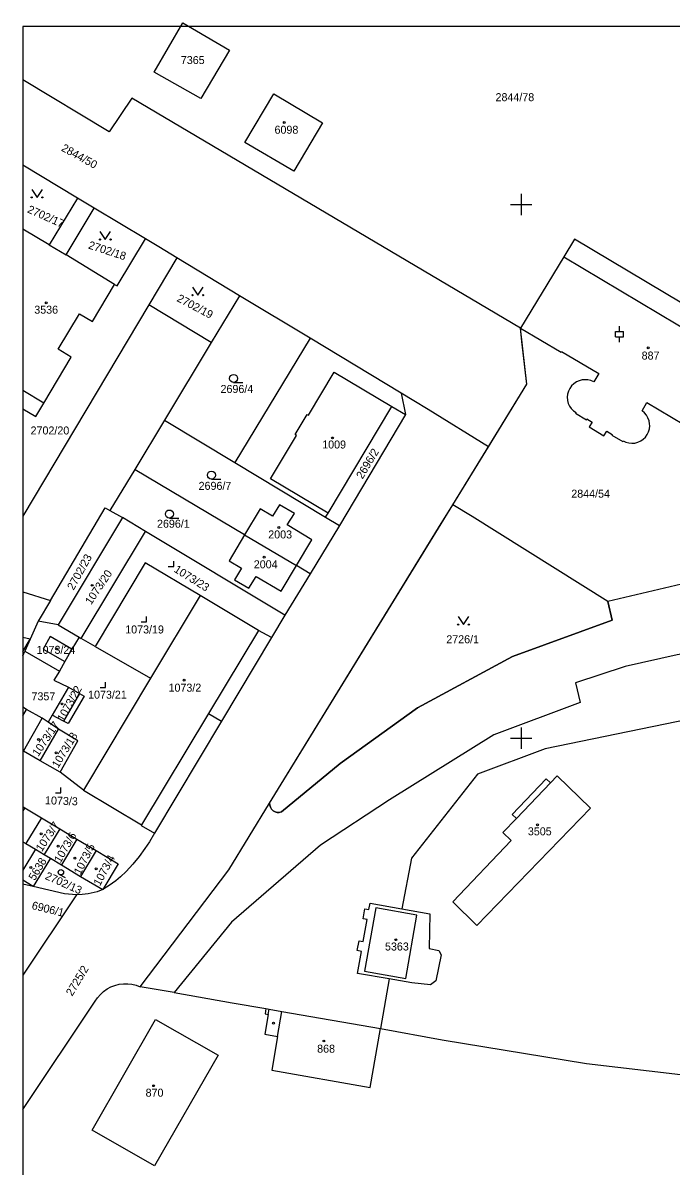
# Model space of a CAD drawing. Extents: x -800194 to -799078, y -1007177 to -1006597.
# Drawn here: x -800193.4 to -800071.9, y -1006980.2 to -1006766 of the extents above; entities that cross this region are included whole.
import ezdxf

# ---------------------------------------------------------------- set-up
doc = ezdxf.new("R2010")
doc.units = 0
for name, color, linetype in [('Legenda 1', 7, 'Continuous'), ('Ramove udaje', 7, 'Continuous'), ('Vrstva 53', 7, 'Continuous'), ('Vrstva 55', 7, 'Continuous'), ('Vrstva 56', 7, 'Continuous'), ('Vrstva 57', 7, 'Continuous'), ('Vrstva 58', 7, 'Continuous'), ('Vrstva 59', 7, 'Continuous')]:
    doc.layers.add(name, color=color, linetype=linetype)

msp = doc.modelspace()

# ---------------------------------------------------------------- linework, layer by layer
at = {"layer": 'Legenda 1'}
msp.add_lwpolyline([(-800193.4, -1007176.65), (-799312.4, -1007176.65), (-799312.4, -1006766.65), (-800193.4, -1006766.65)], close=True, dxfattribs=at)
at = {"layer": 'Ramove udaje'}
for p, q in [((-800100, -1006798), (-800100, -1006802)), ((-800102, -1006800), (-800100, -1006800)), ((-800100, -1006800), (-800098, -1006800)), ((-800100, -1006898), (-800100, -1006902)), ((-800102, -1006900), (-800100, -1006900)), ((-800100, -1006900), (-800098, -1006900))]:
    msp.add_line(p, q, dxfattribs=at)
at = {"layer": 'Vrstva 53'}
msp.add_lwpolyline([(-800067.83, -1006870.66), (-800083.75, -1006874.38), (-800082.93, -1006877.89), (-800101.58, -1006884.73), (-800119.41, -1006894.35), (-800133.89, -1006904.78), (-800144.92, -1006913.85), (-800145.32, -1006913.94), (-800145.72, -1006913.94), (-800146.12, -1006913.83), (-800146.47, -1006913.63), (-800146.77, -1006913.35), (-800147, -1006912.99), (-800147.12, -1006912.61), (-800147.15, -1006912.2), (-800112.81, -1006856.29), (-800098.93, -1006833.67), (-800100.11, -1006823.15), (-800172.96, -1006780.08), (-800177.22, -1006786.39), (-800193.4, -1006776.62)], dxfattribs=at)
at = {"layer": 'Vrstva 55'}
for p, q in [((-800183.18, -1006798.79), (-800193.4, -1006792.65)), ((-800180.01, -1006800.69), (-800183.18, -1006798.79)), ((-800170.41, -1006806.46), (-800180.01, -1006800.69)), ((-800164.51, -1006810.02), (-800169.77, -1006818.83)), ((-800152.8, -1006817.1), (-800164.51, -1006810.02)), ((-800152.8, -1006817.1), (-800158.09, -1006825.87)), ((-800139.57, -1006825.06), (-800152.8, -1006817.1)), ((-800158.09, -1006825.87), (-800169.77, -1006818.83)), ((-800158.09, -1006825.87), (-800166.86, -1006840.41)), ((-800139.57, -1006825.06), (-800153.65, -1006848.37)), ((-800122.47, -1006835.35), (-800139.57, -1006825.06)), ((-800122.47, -1006835.35), (-800121.67, -1006839.36)), ((-800166.86, -1006840.41), (-800172.41, -1006849.68)), ((-800166.86, -1006840.41), (-800153.65, -1006848.37)), ((-800121.67, -1006839.36), (-800134.05, -1006860.17)), ((-800112.81, -1006856.29), (-800106.13, -1006845.4)), ((-800172.41, -1006849.68), (-800177.12, -1006857.35)), ((-800153.65, -1006848.37), (-800136.64, -1006858.61)), ((-800177.12, -1006857.35), (-800174.74, -1006858.64)), ((-800136.64, -1006858.61), (-800134.05, -1006860.17)), ((-800174.74, -1006858.64), (-800186.75, -1006878.76)), ((-800170.43, -1006861.26), (-800174.74, -1006858.64)), ((-800134.05, -1006860.17), (-800139.55, -1006869.21)), ((-800182.47, -1006881.33), (-800170.43, -1006861.26)), ((-800144.27, -1006876.97), (-800170.43, -1006861.26)), ((-800151.83, -1006861.89), (-800142.1, -1006867.68)), ((-800139.55, -1006869.21), (-800144.27, -1006876.97)), ((-800139.55, -1006869.21), (-800142.1, -1006867.68)), ((-800067.83, -1006870.66), (-800083.75, -1006874.38)), ((-800193.4, -1006872.57), (-800188.22, -1006874.2)), ((-800160.18, -1006873.27), (-800169.49, -1006888.81)), ((-800188.22, -1006874.2), (-800190.53, -1006878.1)), ((-800144.27, -1006876.97), (-800146.81, -1006881.14)), ((-800190.53, -1006878.1), (-800192.02, -1006881.48)), ((-800186.75, -1006878.76), (-800190.53, -1006878.1)), ((-800186.75, -1006878.76), (-800182.83, -1006881.12)), ((-800192.02, -1006881.48), (-800193.4, -1006881.15)), ((-800192.02, -1006881.48), (-800193.01, -1006883.73)), ((-800182.83, -1006881.12), (-800182.47, -1006881.33)), ((-800179.85, -1006882.84), (-800182.47, -1006881.33)), ((-800193.4, -1006884.61), (-800193.01, -1006883.73)), ((-800193.01, -1006883.73), (-800186.55, -1006887.44)), ((-800179.85, -1006882.84), (-800169.49, -1006888.81)), ((-800186.55, -1006887.44), (-800187.59, -1006889.15)), ((-800184.82, -1006890.46), (-800187.9, -1006895.7)), ((-800187.59, -1006889.15), (-800184.82, -1006890.46)), ((-800169.49, -1006888.81), (-800182.05, -1006909.75)), ((-800192.7, -1006894.63), (-800193.4, -1006894.24)), ((-800193.4, -1006895.86), (-800192.7, -1006894.63)), ((-800189.78, -1006896.28), (-800192.7, -1006894.63)), ((-800193.28, -1006902.47), (-800189.78, -1006896.28)), ((-800188.68, -1006897.03), (-800189.78, -1006896.28)), ((-800187.9, -1006895.7), (-800188.68, -1006897.03)), ((-800186.7, -1006898.36), (-800188.68, -1006897.03)), ((-800190.15, -1006904.25), (-800186.7, -1006898.36)), ((-800183.1, -1006900.51), (-800186.7, -1006898.36)), ((-800186.38, -1006906.38), (-800183.1, -1006900.51)), ((-800193.28, -1006902.47), (-800193.4, -1006902.4)), ((-800190.15, -1006904.25), (-800193.28, -1006902.47)), ((-800186.38, -1006906.38), (-800190.15, -1006904.25)), ((-800182.05, -1006909.75), (-800186.38, -1006906.38)), ((-800193.05, -1006913.06), (-800193.4, -1006913.64)), ((-800193.05, -1006913.06), (-800189.92, -1006914.94)), ((-800189.92, -1006914.94), (-800192.83, -1006919.78)), ((-800189.92, -1006914.94), (-800186.48, -1006917.01)), ((-800186.48, -1006917.01), (-800189.39, -1006921.85)), ((-800186.48, -1006917.01), (-800183.26, -1006918.94)), ((-800193.4, -1006919.44), (-800192.83, -1006919.78)), ((-800192.83, -1006919.78), (-800191.06, -1006920.85)), ((-800183.26, -1006918.94), (-800186.17, -1006923.78)), ((-800183.26, -1006918.94), (-800179.67, -1006921.09)), ((-800191.06, -1006920.85), (-800193.4, -1006924.74)), ((-800188.23, -1006922.55), (-800191.44, -1006927.83)), ((-800191.06, -1006920.85), (-800189.39, -1006921.85)), ((-800189.39, -1006921.85), (-800188.23, -1006922.55)), ((-800188.23, -1006922.55), (-800186.17, -1006923.78)), ((-800179.67, -1006921.09), (-800182.6, -1006925.93)), ((-800120.56, -1006922.5), (-800122.37, -1006932)), ((-800186.17, -1006923.78), (-800182.6, -1006925.93)), ((-800191.44, -1006927.83), (-800193.4, -1006926.67)), ((-800182.6, -1006925.93), (-800178.43, -1006928.42)), ((-800191.44, -1006927.83), (-800193.4, -1006927.37)), ((-800183.37, -1006929.41), (-800193.4, -1006944.43)), ((-800124.76, -1006945.16), (-800126.38, -1006954.46)), ((-800165.04, -1006947.7), (-800171.39, -1006946.62))]:
    msp.add_line(p, q, dxfattribs=at)
for points in [[(-800163.38, -1006765.95), (-800154.63, -1006771.06), (-800160.01, -1006780.11), (-800168.77, -1006775.17), (-800163.38, -1006765.95)], [(-800100.11, -1006823.15), (-800172.96, -1006780.08), (-800177.22, -1006786.39), (-800193.4, -1006776.62)], [(-800146.37, -1006779.25), (-800137.24, -1006784.69), (-800142.62, -1006793.72), (-800151.76, -1006788.38), (-800146.37, -1006779.25)], [(-800183.18, -1006798.79), (-800188.44, -1006807.58), (-800193.4, -1006804.6)], [(-800176.19, -1006814.96), (-800185.31, -1006809.46), (-800180.01, -1006800.69)], [(-800176.19, -1006814.96), (-800175.72, -1006815.24), (-800170.41, -1006806.46)], [(-800164.51, -1006810.02), (-800167.92, -1006807.96), (-800170.41, -1006806.46)], [(-800020.66, -1006847.86), (-800026.06, -1006844.58), (-800089.97, -1006806.47), (-800092.01, -1006809.83), (-800100.11, -1006823.15)], [(-800193.4, -1006838.29), (-800190.96, -1006839.75), (-800189.46, -1006837.23), (-800184.32, -1006828.6), (-800186.75, -1006827.14), (-800182.78, -1006820.48), (-800180.34, -1006821.93), (-800176.19, -1006814.96)], [(-800169.77, -1006818.83), (-800193.4, -1006858.41)], [(-800106.13, -1006845.4), (-800098.93, -1006833.67), (-800099.83, -1006825.69), (-800100.11, -1006823.15)], [(-800100.11, -1006823.15), (-800092.48, -1006827.68), (-800092.4, -1006827.53), (-800085.43, -1006831.67), (-800086.36, -1006833.24)], [(-800086.36, -1006833.24), (-800086.9, -1006833.01), (-800087.46, -1006832.87), (-800088.05, -1006832.83), (-800088.53, -1006832.88), (-800089.09, -1006833.02), (-800089.63, -1006833.26), (-800090.11, -1006833.59), (-800090.53, -1006833.99), (-800090.88, -1006834.46), (-800091.13, -1006834.97), (-800091.29, -1006835.52), (-800091.35, -1006836.09), (-800091.31, -1006836.66), (-800091.3, -1006836.72), (-800091.15, -1006837.27), (-800090.91, -1006837.79), (-800090.58, -1006838.25), (-800090.17, -1006838.66), (-800089.7, -1006838.98)], [(-800106.13, -1006845.4), (-800117.43, -1006838.45), (-800120.08, -1006836.82), (-800122.47, -1006835.35)], [(-800077.33, -1006838.69), (-800076.4, -1006837.12), (-800069.48, -1006841.22), (-800069.56, -1006841.35), (-800061.89, -1006845.9), (-800061.61, -1006845.43), (-800053.39, -1006850.31), (-800053.68, -1006850.78), (-800042.78, -1006857.25)], [(-800136.64, -1006858.61), (-800136.18, -1006857.85), (-800124.24, -1006837.87), (-800121.67, -1006839.36)], [(-800089.7, -1006838.98), (-800089.78, -1006839.11), (-800087.76, -1006840.33), (-800087.69, -1006840.2), (-800086.68, -1006840.8), (-800087.24, -1006841.68), (-800084.46, -1006843.37), (-800083.93, -1006842.46), (-800082.91, -1006843.08), (-800082.98, -1006843.21), (-800080.94, -1006844.44), (-800080.86, -1006844.31)], [(-800080.86, -1006844.31), (-800080.34, -1006844.55), (-800079.78, -1006844.7), (-800079.21, -1006844.75), (-800078.65, -1006844.71), (-800078.09, -1006844.56), (-800077.57, -1006844.32), (-800077.09, -1006843.99), (-800076.68, -1006843.59), (-800076.35, -1006843.12), (-800076.1, -1006842.6), (-800075.95, -1006842.04), (-800075.89, -1006841.47), (-800075.91, -1006841.1), (-800076.01, -1006840.53), (-800076.22, -1006839.99), (-800076.51, -1006839.49), (-800076.89, -1006839.06), (-800077.33, -1006838.69)], [(-800151.83, -1006861.89), (-800172.32, -1006849.75), (-800172.41, -1006849.68)], [(-800142.1, -1006867.68), (-800139.22, -1006862.87), (-800143.86, -1006860.02), (-800142.5, -1006857.92), (-800145.28, -1006856.27), (-800146.57, -1006858.42), (-800148.9, -1006857.02), (-800151.83, -1006861.89)], [(-800147.15, -1006912.2), (-800114.97, -1006859.8), (-800112.81, -1006856.29)], [(-800083.75, -1006874.38), (-800109.15, -1006858.49), (-800112.81, -1006856.29)], [(-800188.22, -1006874.2), (-800177.98, -1006856.88), (-800177.12, -1006857.35)], [(-800151.83, -1006861.89), (-800154.75, -1006866.76), (-800152.43, -1006868.16), (-800153.72, -1006870.34), (-800151.03, -1006871.91), (-800149.68, -1006869.74), (-800144.98, -1006872.49), (-800142.1, -1006867.68)], [(-800160.18, -1006873.27), (-800170.48, -1006867.17), (-800179.85, -1006882.84)], [(-800146.81, -1006881.14), (-800149.24, -1006879.83), (-800160.18, -1006873.27)], [(-800144.92, -1006913.85), (-800133.89, -1006904.78), (-800119.41, -1006894.35), (-800101.58, -1006884.73), (-800082.93, -1006877.89), (-800083.75, -1006874.38)], [(-799964.79, -1006890.84), (-799979.01, -1006885.96), (-799998.45, -1006881.67), (-800018.08, -1006879.48), (-800038.51, -1006879.76), (-800056.43, -1006881.95), (-800070.76, -1006884.38), (-800080.47, -1006886.59), (-800089.79, -1006889.63), (-800088.91, -1006893.34), (-800105.12, -1006899.41), (-800124.67, -1006911.59), (-800137.62, -1006920.11), (-800154.3, -1006934.53), (-800165.04, -1006947.7)], [(-800193.4, -1006883.76), (-800192.02, -1006881.48)], [(-800182.83, -1006881.12), (-800184.21, -1006883.32), (-800185.51, -1006885.63), (-800186.55, -1006887.44)], [(-800146.81, -1006881.14), (-800156.19, -1006896.85), (-800168.72, -1006917.84)], [(-800184.82, -1006890.46), (-800182.76, -1006891.66), (-800181.9, -1006892.16), (-800184.93, -1006897.3), (-800185.8, -1006896.83), (-800187.9, -1006895.7)], [(-800048.34, -1006892.35), (-800095.49, -1006902.03), (-800108.2, -1006906.76), (-800120.56, -1006922.5)], [(-800094.49, -1006908.41), (-800093.24, -1006907.11), (-800087, -1006913.15), (-800108.28, -1006935.11), (-800112.78, -1006930.68), (-800101.83, -1006919.22), (-800103.39, -1006917.73), (-800100.86, -1006915.08), (-800101.66, -1006914.32), (-800095.28, -1006907.65), (-800094.49, -1006908.41)], [(-800182.05, -1006909.75), (-800171.15, -1006916.28), (-800171.22, -1006916.39), (-800168.72, -1006917.84)], [(-800171.39, -1006946.62), (-800154.78, -1006924.73), (-800147.15, -1006912.2)], [(-800147.15, -1006912.2), (-800147.12, -1006912.61), (-800147, -1006912.99), (-800146.78, -1006913.34), (-800146.77, -1006913.35), (-800146.47, -1006913.63), (-800146.12, -1006913.83), (-800145.72, -1006913.94), (-800145.32, -1006913.94), (-800144.92, -1006913.85)], [(-800193.4, -1006912.85), (-800193.05, -1006913.06)], [(-800168.72, -1006917.84), (-800169.66, -1006919.43), (-800170.52, -1006920.73), (-800171.62, -1006922.22), (-800172.79, -1006923.65), (-800174.04, -1006925.01), (-800175.11, -1006926.02), (-800176, -1006926.76), (-800177.19, -1006927.63), (-800178.43, -1006928.42)], [(-800179.67, -1006921.09), (-800175.54, -1006923.58), (-800178.43, -1006928.42)], [(-800183.37, -1006929.41), (-800185.59, -1006929.21), (-800191.44, -1006927.83)], [(-800178.43, -1006928.42), (-800179.48, -1006928.81), (-800180.04, -1006928.97), (-800181.14, -1006929.22), (-800182.25, -1006929.36), (-800183.37, -1006929.41)], [(-800124.76, -1006945.16), (-800130.67, -1006944.14), (-800129.93, -1006939.99), (-800130.7, -1006939.85), (-800130.36, -1006937.99), (-800129.59, -1006938.12), (-800128.86, -1006934.02), (-800129.62, -1006933.9), (-800129.29, -1006932.03), (-800128.52, -1006932.16), (-800128.31, -1006930.95), (-800122.37, -1006932)], [(-800122.37, -1006932), (-800117.1, -1006932.94), (-800117.23, -1006939.43), (-800115.39, -1006939.82), (-800114.95, -1006940.64), (-800115.98, -1006945.49), (-800117, -1006946.26), (-800120.48, -1006945.9), (-800124.76, -1006945.16)], [(-800179.84, -1006949.35), (-800179.39, -1006948.67), (-800178.86, -1006948.05), (-800178.26, -1006947.5), (-800177.6, -1006947.03), (-800176.89, -1006946.65), (-800176.16, -1006946.36), (-800175.37, -1006946.16), (-800174.56, -1006946.05), (-800173.75, -1006946.05), (-800172.94, -1006946.14), (-800172.15, -1006946.33), (-800171.39, -1006946.62)], [(-800165.04, -1006947.7), (-800154.15, -1006949.62), (-800147.83, -1006950.72)], [(-800193.4, -1006969.65), (-800179.84, -1006949.35)], [(-800147.83, -1006950.72), (-800148, -1006951.71), (-800147.41, -1006951.81), (-800148.05, -1006955.52), (-800145.68, -1006955.92), (-800146.75, -1006962.28), (-800128.29, -1006965.5), (-800126.38, -1006954.46)], [(-800147.83, -1006950.72), (-800147.24, -1006950.83), (-800144.85, -1006951.24), (-800126.38, -1006954.46)], [(-800156.78, -1006959.44), (-800168.69, -1006980.17), (-800180.42, -1006973.53), (-800168.51, -1006952.75), (-800156.78, -1006959.44)], [(-800126.38, -1006954.46), (-800114.82, -1006956.57), (-800087.75, -1006960.99), (-799990.59, -1006972.38), (-799910.85, -1006981.15)]]:
    msp.add_lwpolyline(points, dxfattribs=at)
at = {"layer": 'Vrstva 56'}
for p, q in [((-800188.44, -1006807.58), (-800185.31, -1006809.46)), ((-800092.01, -1006809.83), (-800054.01, -1006832.46)), ((-800139.86, -1006839.49), (-800135.03, -1006831.4)), ((-800135.03, -1006831.4), (-800124.24, -1006837.87)), ((-800189.46, -1006837.23), (-800193.4, -1006834.87)), ((-800142.38, -1006843.12), (-800140.12, -1006839.33)), ((-800140.12, -1006839.33), (-800139.86, -1006839.49)), ((-800146.98, -1006851.4), (-800142.12, -1006843.27)), ((-800142.12, -1006843.27), (-800142.38, -1006843.12)), ((-800136.18, -1006857.85), (-800146.98, -1006851.4)), ((-800149.24, -1006879.83), (-800158.6, -1006895.39)), ((-800188.29, -1006880.97), (-800189.61, -1006883.33)), ((-800184.21, -1006883.32), (-800188.29, -1006880.97)), ((-800189.61, -1006883.33), (-800185.51, -1006885.63)), ((-800182.76, -1006891.66), (-800185.8, -1006896.83)), ((-800158.6, -1006895.39), (-800171.15, -1006916.28)), ((-800158.6, -1006895.39), (-800156.19, -1006896.85)), ((-800100.86, -1006915.08), (-800094.49, -1006908.41)), ((-800127.23, -1006931.83), (-800129.33, -1006943.68)), ((-800119.52, -1006933.21), (-800127.23, -1006931.83)), ((-800121.59, -1006945.08), (-800119.52, -1006933.21)), ((-800129.33, -1006943.68), (-800121.59, -1006945.08)), ((-800147.41, -1006951.81), (-800147.24, -1006950.83)), ((-800145.68, -1006955.92), (-800144.85, -1006951.24))]:
    msp.add_line(p, q, dxfattribs=at)
at = {"layer": 'Vrstva 58'}
for p, q in [((-800082.29, -1006823.83), (-800080.79, -1006823.83)), ((-800082.29, -1006824.83), (-800082.29, -1006823.83)), ((-800081.54, -1006823.83), (-800081.54, -1006822.83)), ((-800080.79, -1006824.83), (-800080.79, -1006823.83)), ((-800082.29, -1006824.83), (-800080.79, -1006824.83)), ((-800081.54, -1006825.83), (-800081.54, -1006824.83)), ((-800153.9, -1006833.35), (-800152.15, -1006833.35)), ((-800158.04, -1006851.47), (-800156.29, -1006851.47)), ((-800165.92, -1006858.76), (-800164.17, -1006858.76)), ((-800165.12, -1006867.84), (-800165.12, -1006866.84)), ((-800166.13, -1006867.84), (-800165.12, -1006867.84)), ((-800170.24, -1006878.2), (-800170.24, -1006877.2)), ((-800171.24, -1006878.2), (-800170.24, -1006878.2)), ((-800178.93, -1006890.56), (-800177.92, -1006890.56)), ((-800177.92, -1006890.56), (-800177.92, -1006889.56)), ((-800186.28, -1006910.27), (-800186.28, -1006909.27)), ((-800187.28, -1006910.27), (-800186.28, -1006910.27)), ((-800186.51, -1006925.6), (-800185.47, -1006926.15))]:
    msp.add_line(p, q, dxfattribs=at)
for points in [[(-800191.74, -1006797.17), (-800190.74, -1006798.67), (-800189.74, -1006797.17)], [(-800178.94, -1006805.05), (-800177.94, -1006806.55), (-800176.94, -1006805.05)], [(-800161.61, -1006815.49), (-800160.61, -1006816.99), (-800159.61, -1006815.49)], [(-800111.8, -1006877.25), (-800110.8, -1006878.75), (-800109.8, -1006877.25)]]:
    msp.add_lwpolyline(points, dxfattribs=at)
for centre, radius in [((-800191.74, -1006798.67), 0.1), ((-800189.74, -1006798.67), 0.1), ((-800178.94, -1006806.55), 0.1), ((-800176.94, -1006806.55), 0.1), ((-800161.61, -1006816.99), 0.1), ((-800159.61, -1006816.99), 0.1), ((-800153.9, -1006832.6), 0.75), ((-800158.04, -1006850.72), 0.75), ((-800165.92, -1006858.01), 0.75), ((-800111.8, -1006878.75), 0.1), ((-800109.8, -1006878.75), 0.1), ((-800186.27, -1006925.16), 0.502)]:
    msp.add_circle(centre, radius, dxfattribs=at)
at = {"layer": 'Vrstva 59'}
for centre in [(-800144.39, -1006784.64), (-800189.01, -1006818.41), (-800076.15, -1006826.87), (-800135.34, -1006843.76), (-800145.42, -1006860.54), (-800148.15, -1006866.1), (-800180.42, -1006871.38), (-800187.09, -1006883.31), (-800163.18, -1006889.16), (-800186.06, -1006893.62), (-800190.48, -1006900.28), (-800187.14, -1006902.79), (-800096.93, -1006916.27), (-800189.96, -1006917.94), (-800186.79, -1006920.28), (-800183.63, -1006922.51), (-800191.89, -1006924.28), (-800179.65, -1006924.5), (-800123.47, -1006937.8), (-800146.41, -1006953.43), (-800136.95, -1006956.79), (-800168.88, -1006965.17)]:
    msp.add_circle(centre, 0.175, dxfattribs=at)

# ---------------------------------------------------------------- texts
at = {"layer": 'Vrstva 57'}
for s, p in [('7365', (-800163.78, -1006773.67)), ('2844/78', (-800104.79, -1006780.63)), ('6098', (-800146.22, -1006786.73)), ('3536', (-800191.26, -1006820.46)), ('887', (-800077.4, -1006829.06)), ('2696/4', (-800156.34, -1006835.32)), ('2702/20', (-800191.95, -1006843.1)), ('1009', (-800137.28, -1006845.73)), ('2696/7', (-800160.45, -1006853.48)), ('2844/54', (-800090.59, -1006854.95)), ('2696/1', (-800168.25, -1006860.58)), ('2003', (-800147.4, -1006862.59)), ('2004', (-800150.11, -1006868.19)), ('1073/19', (-800174.21, -1006880.4)), ('2726/1', (-800114.02, -1006882.24)), ('1073/24', (-800190.82, -1006884.22)), ('1073/2', (-800166.09, -1006891.31)), ('7357', (-800191.78, -1006892.93)), ('1073/21', (-800181.17, -1006892.62)), ('3505', (-800098.73, -1006918.24)), ('5363', (-800125.51, -1006939.83)), ('868', (-800138.23, -1006958.98)), ('870', (-800170.39, -1006967.23))]:
    msp.add_text(s, height=1.5, dxfattribs=at).set_placement(p)
for s, rotation, p in [('2844/50', 331, (-800186.32, -1006789.84)), ('2702/17', 336, (-800192.68, -1006801.44)), ('2702/18', 342, (-800181.24, -1006808.22)), ('2702/19', 332, (-800164.66, -1006818.05)), ('2696/2', 59, (-800129.73, -1006851.57)), ('2702/23', 61, (-800183.89, -1006872.4)), ('1073/20', 56, (-800180.61, -1006875.14)), ('1073/23', 328, (-800165.2, -1006868.76)), ('1073/22', 61, (-800185.78, -1006897.06)), ('1073/17', 56, (-800190.51, -1006903.56)), ('1073/18', 59, (-800186.78, -1006905.74)), ('1073/3', 358, (-800189.26, -1006912.41)), ('1073/7', 56, (-800189.86, -1006921.42)), ('1073/6', 60, (-800186.35, -1006923.53)), ('1073/5', 63, (-800182.61, -1006925.75)), ('5638', 59, (-800191.17, -1006926.84)), ('1073/4', 62, (-800178.95, -1006927.85)), ('2702/13', 336, (-800189.37, -1006926.38)), ('6906/1', 346, (-800191.84, -1006932.03)), ('2725/2', 59, (-800184.15, -1006948.49))]:
    msp.add_text(s, height=1.5, rotation=rotation, dxfattribs=at).set_placement(p)

doc.saveas('drawing.dxf')
